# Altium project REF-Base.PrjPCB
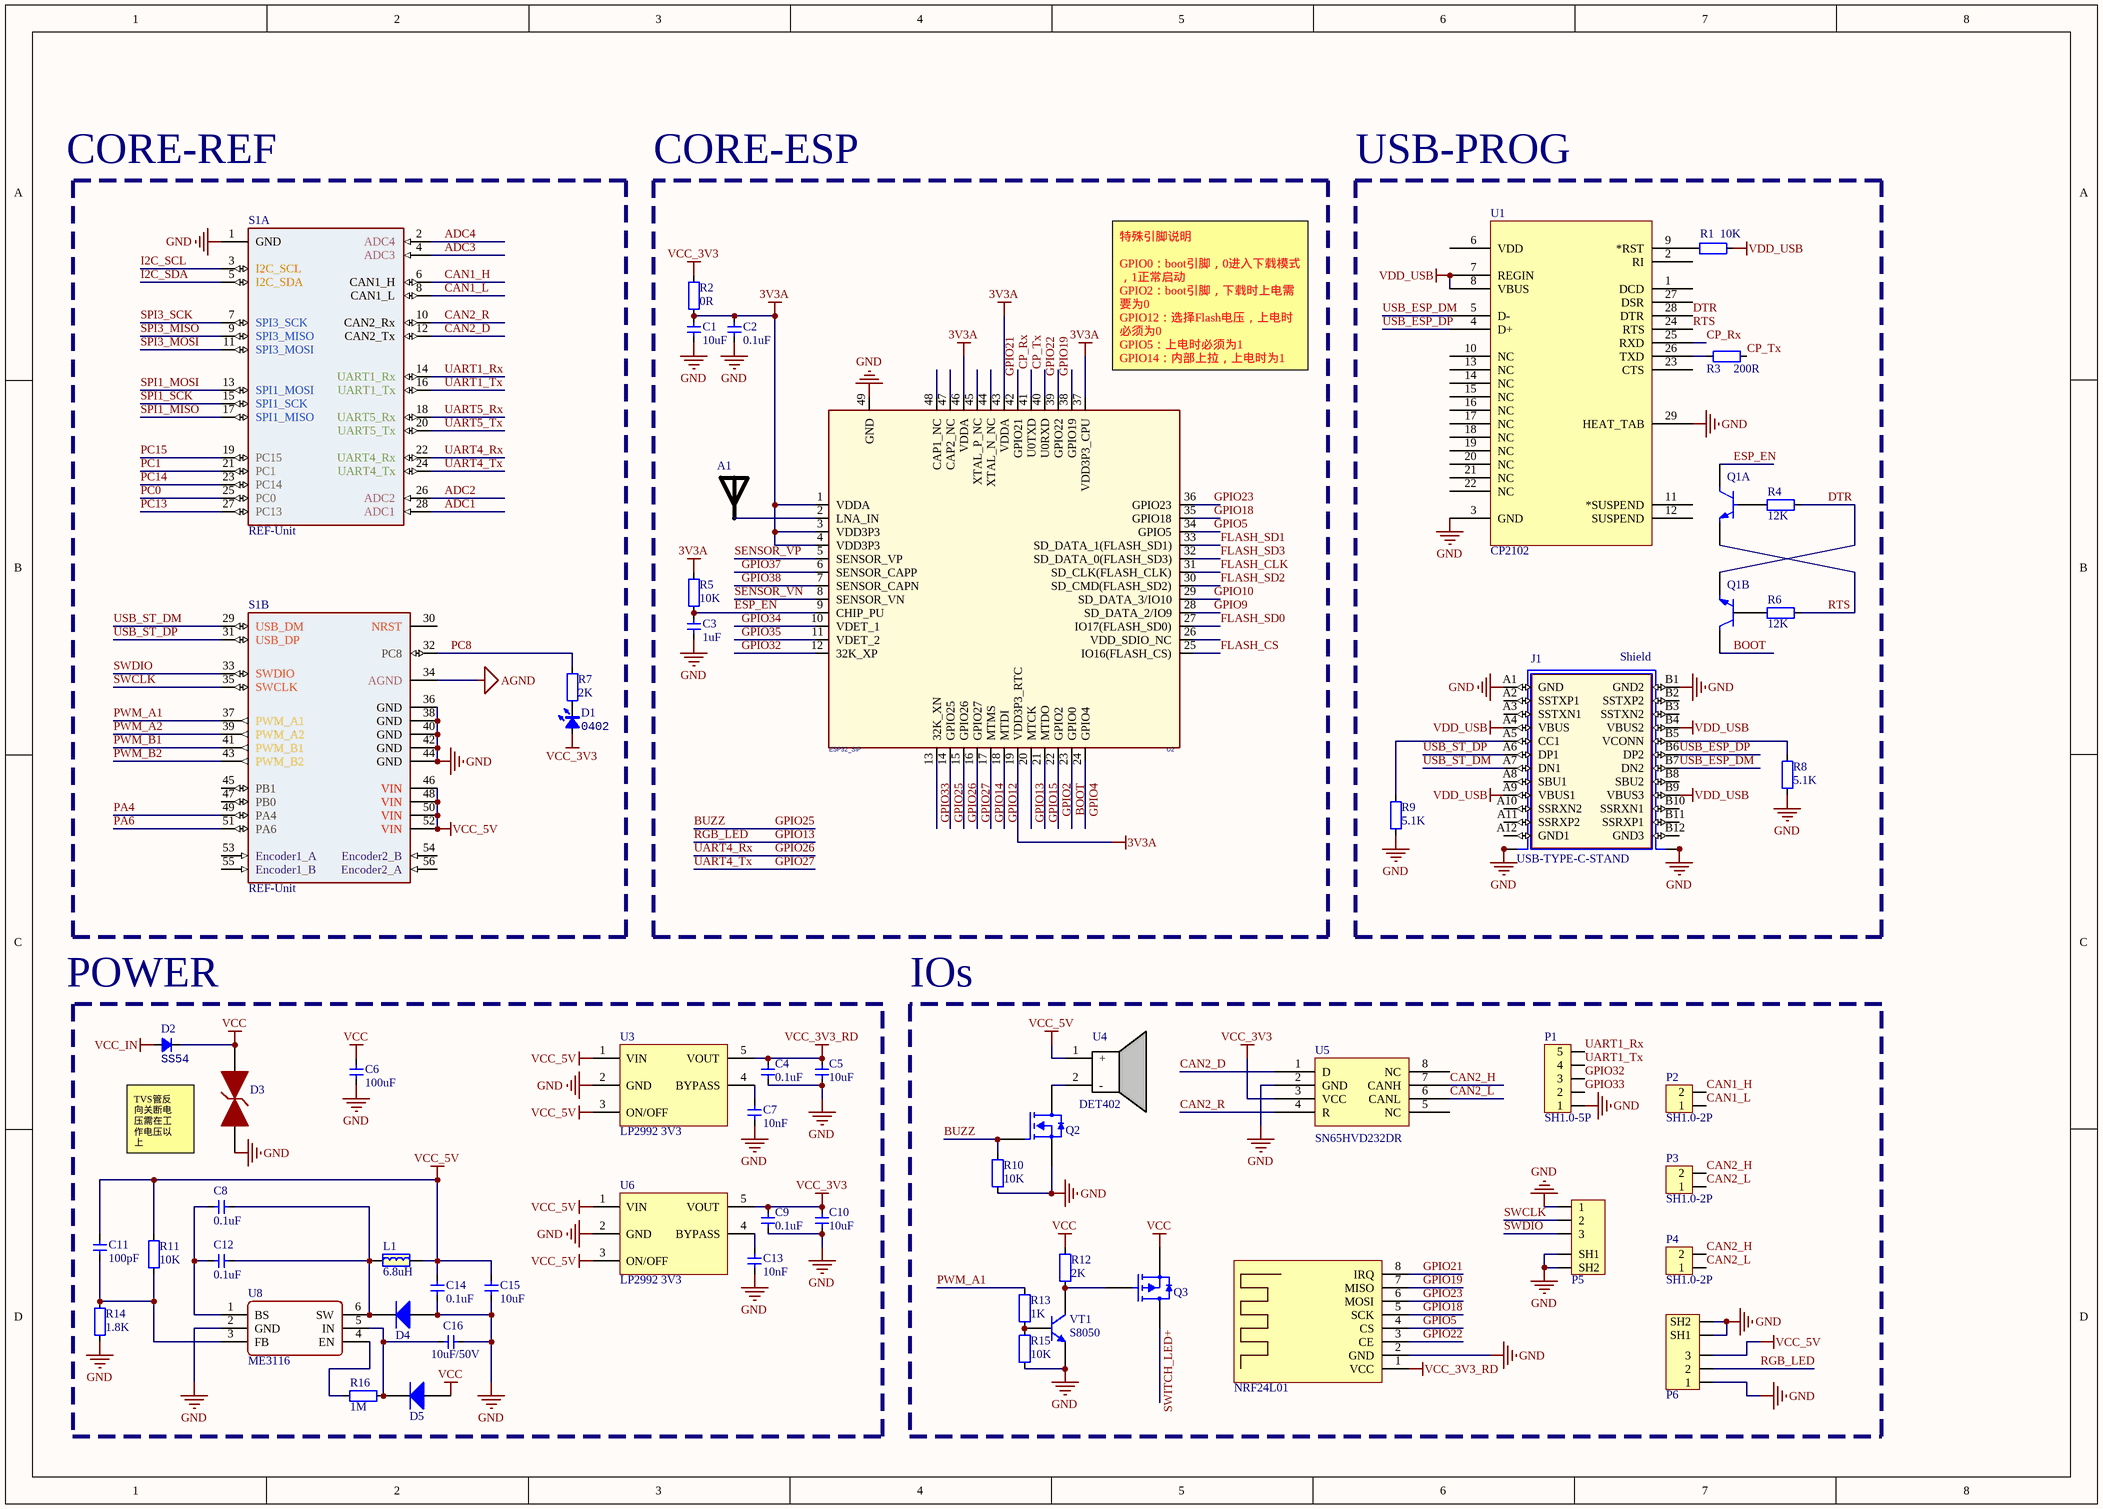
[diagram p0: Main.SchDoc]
1 sheet, 59 parts. Net scope: hierarchical (ports join the sheet entries above them; power ports are global).
Board file: REF-Base.PcbDoc

## Sheet Main.SchDoc
size A3; SheetNumber: 1

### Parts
A1  RAINSUN  [ANT-Rainsun-AN5120]  (value not drawn)
C1  10uF  [CAP_0402]
C2  0.1uF  [CAP_0402]
C3  1uF  [CAP_0402]
C4  0.1uF  [CAP_0402]
C5  10uF  [CAP_0402]
C6  100uF  [1206-CAP]
C7  10nF  [CAP_0402]
C8  0.1uF  [CAP_0402]
C9  0.1uF  [CAP_0402]
C10  10uF  [CAP_0402]
C11  100pF  [CAP_0402]
C12  0.1uF  [CAP_0402]
C13  10nF  [CAP_0402]
C14  0.1uF  [CAP_0402]
C15  10uF  [CAP_0402]
C16  10uF/50V  [CAP_0402]
D1  Type: 0402  [LED_0402_RED]  (hidden comment: color?)
D2  SS54  [DO-214AC]
D3  SMBJ28CA  [SMBJ-CA_MFG]  (value not drawn)
D4  二极管-5819W  [SOD-323]  (value not drawn)
D5  二极管-5819W  [SOD-323]  (value not drawn)
J1  USB-TYPE-C-STAND  [USB-TYPE-C-STAND]
L1  6.8uH  [IND-201612]
P1  SH1.0-5P  [SH1.0-5P]
P2  SH1.0-2P  [SH1.0-2P]
P3  SH1.0-2P  [SH1.0-2P]
P4  SH1.0-2P  [SH1.0-2P]
P5  SH1.0-3P  [SH1.0-3P]  (value not drawn)
P6  SH1.0-3P  [SH1.0-3P]  (value not drawn)
Q1  BC847BVC-7  [SOT563-6]  (value not drawn)  (parts A,B of 2)
Q2  AO3400A  [SOT23-3]  (value not drawn)
Q3  AO3401A  [SOT23-3]  (value not drawn)
R1  10K  [RES_0402]
R2  0R  [RES_0402]
R3  200R  [RES_0402]
R4  12K  [RES_0402]
R5  10K  [RES_0402]
R6  12K  [RES_0402]
R7  2K  [RES_0402]
R8  5.1K  [RES_0402]
R9  5.1K  [RES_0402]
R10  10K  [RES_0402]
R11  10K  [RES_0402]
R12  2K  [RES_0402]
R13  1K  [RES_0402]
R14  1.8K  [RES_0402]
R15  10K  [RES_0402]
R16  1M  [RES_0402]
S1  REF-Unit  [REF-UNIT]  (parts A,B of 2)
U1  CP2102  [QFN-28]
U2  ESP32_SIP  [QFN-48_7X7]
U3  LP2992 3V3  [SOT23-5]
U4  DET402  [DET402]
U5  Manufacturer Part Number: SN65HVD232DR  [SO-8]  (hidden comment: SN65HVD232D)
U6  LP2992 3V3  [SOT23-5]
U7  NRF24L01  [NRF24L01-MODULE]
U8  ME3116  [SOT23-6]
VT1  S8050  [SMT_TRIODE_NPN]

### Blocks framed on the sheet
CORE-ESP: A1 C1-C3 R2 R5 U2
USB-PROG: J1 Q1 R1 R3 R4 R6 R8 R9 U1
IOs: P1-P6 Q2 Q3 R10 R12 R13 R15 U4 U5 U7 VT1

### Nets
3V3A: C1.2 C2.2 R2.2 R5.1 U2.1(VDDA) U2.3(VDD3P3) U2.4(VDD3P3) U2.19(VDD3P3_RTC) U2.37(VDD3P3_CPU) U2.43(VDDA) U2.46(VDDA)
AGND: S1.34(AGND)
GND: C1.1 C2.1 C3.2 C4.1 C5.1 C6.1 C7.1 C9.1 C10.1 C13.1 C14.1 C15.1 C16.1 D3.1 D4.1(A) J1.A1(GND) J1.B1(GND2) J1.S1(SHIELD) J1.S2(SHIELD) J1.S3(SHIELD1) J1.S4(SHIELD1) P1.1 P5.1 P5.SH1 P5.SH2 P6.1 P6.SH1 P6.SH2 Q2.2(S) R8.2 R9.2 R10.1 R14.1 R15.2 S1.1(GND) S1.36(GND) S1.38(GND) S1.40(GND) S1.42(GND) S1.44(GND) U1.3(GND) U1.29(HEAT_TAB) U2.49(GND) U3.2(GND) U5.2(GND) U6.2(GND) U7.2(GND) U8.2(GND) VT1.2(E)
VCC: C6.2 D2.2(K) D3.2 D5.1(A) Q3.2(S) R12.2
VCC_3V3: C9.2 C10.2 D1.1(A) R2.1 U5.3(VCC) U6.5(VOUT)
VCC_3V3_RD: C4.2 C5.2 U3.5(VOUT) U7.1(VCC)
VCC_5V: C11.1 C14.2 C15.2 L1.2 P6.3 R11.2 S1.46(VIN) S1.48(VIN) S1.50(VIN) S1.52(VIN) U3.1(VIN) U3.3(ON/OFF) U4.1(+) U6.1(VIN) U6.3(ON/OFF)
VCC_IN: D2.1(A)
VDD_USB: J1.A4(VBUS) J1.A9(VBUS1) J1.B4(VBUS2) J1.B9(VBUS3) R1.1 U1.7(REGIN) U1.8(VBUS)
ADC1: S1.28(ADC1)  [project net ADC1_1]
ADC2: S1.26(ADC2)  [project net ADC2_1]
ADC3: S1.4(ADC3)  [project net ADC3_1]
ADC4: S1.2(ADC4)  [project net ADC4_1]
BOOT: Q1.3(C2) U2.23(GPIO0)  [project net BOOT_1]
BUZZ: Q2.1(G) R10.2 U2.14(GPIO25)  [also labelled GPIO25]  [project net BUZZ_1]
CAN1_H: P2.2 S1.6(CAN1_H)  [project net CAN1_H_1]
CAN1_L: P2.1 S1.8(CAN1_L)  [project net CAN1_L_1]
CAN2_D: S1.12(CAN2_Tx) U5.1(D)  [project net CAN2_D_1]
CAN2_H: P3.2 P4.2 U5.7(CANH)  [project net CAN2_H_1]
CAN2_L: P3.1 P4.1 U5.6(CANL)  [project net CAN2_L_1]
CAN2_R: S1.10(CAN2_Rx) U5.4(R)  [project net CAN2_R_1]
CP_Rx: U1.25(RXD) U2.41(U0TXD)  [project net CP_Rx_1]
CP_Tx: R3.1 U2.40(U0RXD)  [project net CP_Tx_1]
DTR: Q1.4(E2) R4.1 U1.28(DTR)  [project net DTR_1]
ESP_EN: C3.1 Q1.6(C1) R5.2 U2.9(CHIP_PU)  [project net ESP_EN_1]
FLASH_CLK: U2.31(SD_CLK(FLASH_CLK))  [project net FLASH_CLK_1]
FLASH_CS: U2.25(IO16(FLASH_CS))  [project net FLASH_CS_1]
FLASH_SD0: U2.27(IO17(FLASH_SD0))  [project net FLASH_SD0_1]
FLASH_SD1: U2.33(SD_DATA_1(FLASH_SD1))  [project net FLASH_SD1_1]
FLASH_SD2: U2.30(SD_CMD(FLASH_SD2))  [project net FLASH_SD2_1]
FLASH_SD3: U2.32(SD_DATA_0(FLASH_SD3))  [project net FLASH_SD3_1]
GPIO2: U2.22(GPIO2)  [project net GPIO2_1]
GPIO4: U2.24(GPIO4)  [project net GPIO4_1]
GPIO5: U2.34(GPIO5) U7.4(CS)  [project net GPIO5_1]
GPIO9: U2.28(SD_DATA_2/IO9)  [project net GPIO9_1]
GPIO10: U2.29(SD_DATA_3/IO10)  [project net GPIO10_1]
GPIO12: U2.18(MTDI)  [project net GPIO12_1]
GPIO13: P6.2 U2.20(MTCK)  [also labelled RGB_LED]  [project net GPIO13_1]
GPIO14: U2.17(MTMS)  [project net GPIO14_1]
GPIO15: U2.21(MTDO)  [project net GPIO15_1]
GPIO18: U2.35(GPIO18) U7.5(SCK)  [project net GPIO18_1]
GPIO19: U2.38(GPIO19) U7.7(MISO)  [project net GPIO19_1]
GPIO21: U2.42(GPIO21) U7.8(IRQ)  [project net GPIO21_1]
GPIO22: U2.39(GPIO22) U7.3(CE)  [project net GPIO22_1]
GPIO23: U2.36(GPIO23) U7.6(MOSI)  [project net GPIO23_1]
GPIO26: S1.22(UART4_Rx) U2.15(GPIO26)  [also labelled UART4_Rx]  [project net GPIO26_1]
GPIO27: S1.24(UART4_Tx) U2.16(GPIO27)  [also labelled UART4_Tx]  [project net GPIO27_1]
GPIO32: P1.3 U2.12(32K_XP)  [project net GPIO32_1]
GPIO33: P1.2 U2.13(32K_XN)  [project net GPIO33_1]
GPIO34: U2.10(VDET_1)  [project net GPIO34_1]
GPIO35: U2.11(VDET_2)  [project net GPIO35_1]
GPIO37: U2.6(SENSOR_CAPP)  [project net GPIO37_1]
GPIO38: U2.7(SENSOR_CAPN)  [project net GPIO38_1]
I2C_SCL: S1.3(I2C_SCL)  [project net I2C_SCL_1]
I2C_SDA: S1.5(I2C_SDA)  [project net I2C_SDA_1]
PA4: S1.49(PA4)  [project net PA4_1]
PA6: S1.51(PA6)  [project net PA6_1]
PC0: S1.25(PC0)  [project net PC0_1]
PC1: S1.21(PC1)  [project net PC1_1]
PC8: R7.1 S1.32(PC8)  [project net PC8_1]
PC13: S1.27(PC13)  [project net PC13_1]
PC14: S1.23(PC14)  [project net PC14_1]
PC15: S1.19(PC15)  [project net PC15_1]
PWM_A1: R13.1 S1.37(PWM_A1)  [project net PWM_A1_1]
PWM_A2: S1.39(PWM_A2)  [project net PWM_A2_1]
PWM_B1: S1.41(PWM_B1)  [project net PWM_B1_1]
PWM_B2: S1.43(PWM_B2)  [project net PWM_B2_1]
RTS: Q1.1(E1) R6.1 U1.24(RTS)  [project net RTS_1]
SENSOR_VN: U2.8(SENSOR_VN)  [project net SENSOR_VN_1]
SENSOR_VP: U2.5(SENSOR_VP)  [project net SENSOR_VP_1]
SPI1_MISO: S1.17(SPI1_MISO)  [project net SPI1_MISO_1]
SPI1_MOSI: S1.13(SPI1_MOSI)  [project net SPI1_MOSI_1]
SPI1_SCK: S1.15(SPI1_SCK)  [project net SPI1_SCK_1]
SPI3_MISO: S1.9(SPI3_MISO)  [project net SPI3_MISO_1]
SPI3_MOSI: S1.11(SPI3_MOSI)  [project net SPI3_MOSI_1]
SPI3_SCK: S1.7(SPI3_SCK)  [project net SPI3_SCK_1]
SWCLK: P5.2 S1.35(SWCLK)  [project net SWCLK_1]
SWDIO: P5.3 S1.33(SWDIO)  [project net SWDIO_1]
SWITCH_LED+: Q3.3(D)  [project net SWITCH_LED+_1]
UART1_Rx: P1.5 S1.14(UART1_Rx)  [project net UART1_Rx_1]
UART1_Tx: P1.4 S1.16(UART1_Tx)  [project net UART1_Tx_1]
UART5_Rx: S1.18(UART5_Rx)  [project net UART5_Rx_1]
UART5_Tx: S1.20(UART5_Tx)  [project net UART5_Tx_1]
USB_ESP_DM: J1.B7(DN2) U1.5(D-)  [project net USB_ESP_DM_1]
USB_ESP_DP: J1.B6(DP2) U1.4(D+)  [project net USB_ESP_DP_1]
USB_ST_DM: J1.A7(DN1) S1.29(USB_DM)  [project net USB_ST_DM_1]
USB_ST_DP: J1.A6(DP1) S1.31(USB_DP)  [project net USB_ST_DP_1]
NetA1_1: A1.1 U2.2(LNA_IN)
NetC7_2: C7.2 U3.4(BYPASS)
NetC8_1: C8.1 C12.1 D4.2(K) L1.1 U8.6(SW)
NetC8_2: C8.2 C12.2 U8.1(BS)
NetC11_2: C11.2 R11.1 R14.2 U8.3(FB)
NetC13_2: C13.2 U6.4(BYPASS)
NetC16_2: C16.2 D5.2(K) R16.1 U8.5(IN)
NetD1_2: D1.2(K) R7.2
NetJ1_A5: J1.A5(CC1) R9.1
NetJ1_B5: J1.B5(VCONN) R8.1
NetQ1_2: Q1.2(B1) R4.2
NetQ1_5: Q1.5(B2) R6.2
NetQ2_3: Q2.3(D) U4.2(-)
NetQ3_1: Q3.1(G) R12.1 VT1.3(C)
NetR1_2: R1.2 U1.9(*RST)
NetR3_2: R3.2 U1.26(TXD)
NetR13_2: R13.2 R15.1 VT1.1(B)
NetR16_2: R16.2 U8.4(EN)

Not connected (* = marked no-connect by the designer): J1 A2(SSTXP1) A3(SSTXN1) A8(SBU1) A10(SSRXN2) A11(SSRXP2) A12(GND1) B2(SSTXP2) B3(SSTXN2) B8(SBU2) B10(SSRXN1) B11(SSRXP1) B12(GND3); S1 30(NRST) 45(PB1) 47(PB0) 53(Encoder1_A) 54(Encoder2_B) 55(Encoder1_B) 56(Encoder2_A); U1 1(DCD) 2(RI) 6(VDD) 10(NC) 11(*SUSPEND) 12(SUSPEND) 13(NC) 14(NC) 15(NC) 16(NC) 17(NC) 18(NC) 19(NC) 20(NC) 21(NC) 22(NC) 23(CTS) 27(DSR); U2 26(VDD_SDIO_NC) 44(XTAL_N_NC) 45(XTAL_P_NC) 47(CAP2_NC) 48(CAP1_NC); U5 5(NC) 8(NC)

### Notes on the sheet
- CORE-REF
- (near U2) 特殊引脚说明
  GPIO0：boot引脚，0进入下载模式，1正常启动
  GPIO2：boot引脚，下载时上电需要为0
  GPIO12：选择Flash电压，上电时必须为0
  GPIO5：上电时必须为1
  GPIO14：内部上拉，上电时为1
  GPIO15：上电时必须为1
- (near D2) POWER
- TVS管反
  向关断电
  压需在工
  作电压以
  上

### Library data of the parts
A1 = ANT-Rainsun-AP5120
C1-C5 C7-C16 = 电容-0402: Capacitor; Value: 0.1u
C6 = 电容-1206: Capacitor; Value: 0.1u
D1 = LED_0402: LED
D2 = Diode_SMA: Diode; Type: SMA
D4 D5 = 二极管-5819W: 40V
J1 = USB-TYPE-C-STAND: MP: 632722110112; MF: Wurth Electronics
L1 = 电感-201612
P5 P6 = SH1.0-3P: Header
Q2 = AO3400A: N-MOS
Q3 = AO3401A: P-MOS
R1-R16 = 电阻-0402: Resistor; Value: 22R
S1 = REF-Unit: Robot Embedded Framework based on STM43F405RGT6.
U1 = CP2102: USB转TTL; PART DESC: SINGLE-CHIP USB TO UART BRIDGE, QFN28, RoHS.; MFG #1: SILICON LABS
U2 = ESP32-PICO
U3 U6 = LP2992: LDO
U5 = SN65HVD232D: Manufacturer: Texas Instruments; Protocol: CAN; Number of Drivers/Receivers: 1/1; Duplex: Half; Data Rate: 1Mbps; Voltage - Supply: 3 V ~ 3.6 V
U7 = NRF24L01模块
U8 = ME3116: DC-DC
VT1 = SMT_TRIODE_NPN: Surface mount NPN transistor, package SOT-23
